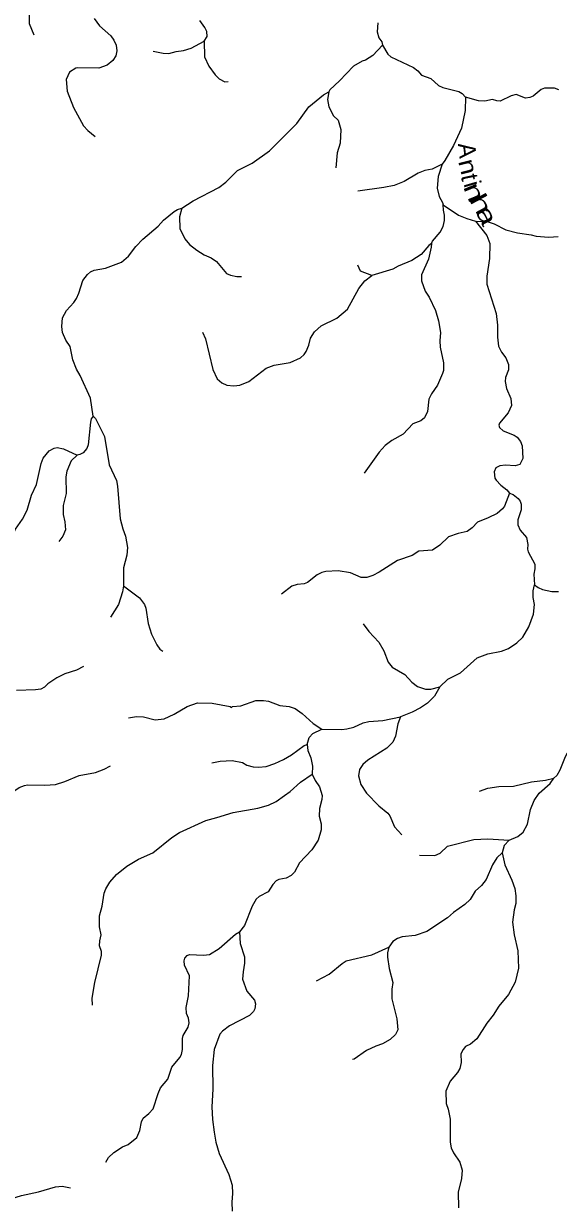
# Model space of a CAD drawing. Extents: x 577 to 602.9, y 7483.8 to 7511.6.
# Drawn here: x 580.64 to 583.13, y 7488.33 to 7493.84 of the extents above; entities that cross this region are included whole.
import ezdxf
from ezdxf.enums import TextEntityAlignment as Align

# ---------------------------------------------------------------- set-up
doc = ezdxf.new("R2010")
doc.units = 0
doc.header["$LTSCALE"] = 0.032
doc.layers.add('61', color=7, linetype='Continuous')
doc.layers.add('7', color=7, linetype='Continuous', lineweight=25)

msp = doc.modelspace()

# ---------------------------------------------------------------- linework, layer by layer
at = {"layer": '7'}
for points in [[(580.6851, 7493.7847), (580.6631, 7493.8367), (580.6631, 7493.8906), (580.668, 7493.911), (580.6892, 7493.9535), (580.6933, 7493.9699), (580.6868, 7494.0516), (580.695, 7494.095), (580.704, 7494.1072), (580.7693, 7494.1399), (580.798, 7494.1644)], [(580.9655, 7493.8612), (580.9892, 7493.8285), (581.0424, 7493.7811), (581.0571, 7493.7615), (581.0677, 7493.7377), (581.071, 7493.7116), (581.0652, 7493.6879), (581.0514, 7493.6666), (581.026, 7493.6446), (580.9868, 7493.6307), (580.8862, 7493.6323), (580.8789, 7493.6299), (580.8495, 7493.6127), (580.8339, 7493.5775), (580.8388, 7493.5236), (580.8683, 7493.4468), (580.9157, 7493.3617), (580.9353, 7493.3397), (580.9688, 7493.3117)], [(581.4764, 7493.7557), (581.4911, 7493.7778), (581.4887, 7493.8007), (581.4797, 7493.8203), (581.4568, 7493.853)], [(582.2856, 7493.8424), (582.2824, 7493.7991), (582.2905, 7493.7721), (582.3036, 7493.7533), (582.3074, 7493.738)], [(581.2392, 7493.7092), (581.2868, 7493.7001), (581.3129, 7493.6993), (581.3473, 7493.7083), (581.3808, 7493.7124), (581.4167, 7493.7239), (581.4764, 7493.7557)], [(581.4764, 7493.7557), (581.4789, 7493.6838), (581.4985, 7493.6405), (581.5279, 7493.5996), (581.5475, 7493.5808), (581.5729, 7493.5677), (581.5888, 7493.5686)], [(582.3074, 7493.738), (582.2619, 7493.6895), (582.2284, 7493.6675), (582.2121, 7493.6625), (582.172, 7493.6397), (582.1066, 7493.571), (582.0625, 7493.5301), (582.0568, 7493.5203)], [(582.3074, 7493.738), (582.3314, 7493.6952), (582.3453, 7493.6838), (582.4508, 7493.6331), (582.4712, 7493.6184), (582.4892, 7493.598), (582.5317, 7493.5824), (582.5676, 7493.5497), (582.5881, 7493.5399), (582.6633, 7493.522), (582.678, 7493.513), (582.6943, 7493.4958)], [(583.1276, 7493.5301), (583.1079, 7493.5367), (583.0614, 7493.5375), (583.0466, 7493.5309), (583.009, 7493.4999), (582.9935, 7493.4942), (582.9731, 7493.4909), (582.9298, 7493.5072), (582.906, 7493.5023), (582.8554, 7493.477), (582.839, 7493.4778), (582.8194, 7493.4844), (582.7834, 7493.477), (582.754, 7493.4786), (582.6943, 7493.4958)], [(581.3734, 7492.9784), (581.4257, 7493.0119), (581.5451, 7493.0748), (581.5786, 7493.1002), (581.6325, 7493.1541), (581.7004, 7493.1876), (581.7813, 7493.2457), (581.9088, 7493.3724), (581.9636, 7493.45), (582.0322, 7493.5064), (582.0568, 7493.5203)], [(582.0568, 7493.5203), (582.051, 7493.4844), (582.0568, 7493.45), (582.0796, 7493.4083), (582.1001, 7493.3879), (582.1132, 7493.3446), (582.1107, 7493.2808), (582.096, 7493.2367), (582.0906, 7493.166)], [(582.6943, 7493.4958), (582.6927, 7493.4337), (582.6747, 7493.3511), (582.6371, 7493.2702), (582.5979, 7493.1999), (582.5848, 7493.1835)], [(582.5848, 7493.1835), (582.5382, 7493.1607), (582.5039, 7493.1541), (582.4728, 7493.1419), (582.4082, 7493.1034), (582.3617, 7493.0846), (582.3134, 7493.074), (582.193, 7493.0579)], [(582.5848, 7493.1835), (582.5668, 7493.1255), (582.5619, 7493.0724), (582.5717, 7493.0323), (582.5873, 7493.0054), (582.5897, 7492.9939)], [(580.96, 7492.0097), (580.9484, 7492.0939), (580.9001, 7492.1986), (580.8821, 7492.228), (580.8658, 7492.2721), (580.8527, 7492.3343), (580.8331, 7492.3637), (580.8176, 7492.3988), (580.8143, 7492.4274), (580.8176, 7492.4683), (580.8364, 7492.5018), (580.8699, 7492.5386), (580.8821, 7492.5574), (580.8936, 7492.5819), (580.9116, 7492.6416), (580.9345, 7492.6702), (580.9475, 7492.6817), (580.9647, 7492.6898), (581.0178, 7492.6988), (581.0914, 7492.7274), (581.1249, 7492.7544), (581.1592, 7492.7994), (581.1919, 7492.8337), (581.2622, 7492.895), (581.2876, 7492.922), (581.3374, 7492.9628), (581.353, 7492.9718), (581.3734, 7492.9784)], [(581.3734, 7492.9784), (581.3628, 7492.9375), (581.3636, 7492.8836), (581.3865, 7492.8361), (581.4094, 7492.81), (581.4421, 7492.783), (581.4772, 7492.7618), (581.5091, 7492.7479), (581.5344, 7492.7299), (581.5802, 7492.6743), (581.5998, 7492.6661), (581.6293, 7492.6604), (581.6505, 7492.6601)], [(582.5358, 7492.8141), (582.5398, 7492.8255), (582.5758, 7492.8672), (582.5897, 7492.8934), (582.5963, 7492.9203), (582.5963, 7492.9457), (582.5913, 7492.9686), (582.5897, 7492.9939)], [(582.5897, 7492.9939), (582.6616, 7492.9465), (582.7001, 7492.9302), (582.7409, 7492.9187)], [(582.7409, 7492.9187), (582.7941, 7492.9163), (582.8268, 7492.9056), (582.8815, 7492.877), (582.9363, 7492.8631), (583, 7492.8549), (583.0229, 7492.8484), (583.0818, 7492.8435), (583.1251, 7492.8469)], [(582.7409, 7492.9187), (582.7924, 7492.8517), (582.8071, 7492.8133), (582.8055, 7492.7438), (582.7924, 7492.662), (582.7924, 7492.6253), (582.8366, 7492.4879), (582.8431, 7492.434), (582.8431, 7492.3776), (582.848, 7492.3359), (582.8611, 7492.3073), (582.8815, 7492.2819), (582.8938, 7492.2509), (582.8938, 7492.2255), (582.8799, 7492.1904), (582.8791, 7492.1716), (582.8848, 7492.1381), (582.9052, 7492.0923), (582.9085, 7492.0588), (582.8922, 7492.0253), (582.8513, 7491.9771), (582.8488, 7491.9672), (582.8521, 7491.9566), (582.8693, 7491.9411), (582.9208, 7491.9215), (582.9347, 7491.9117), (582.9494, 7491.8912), (582.9575, 7491.8716), (582.9608, 7491.8128), (582.9469, 7491.785), (582.9248, 7491.7784), (582.8799, 7491.7809), (582.8529, 7491.7776), (582.8349, 7491.7694), (582.8268, 7491.7506), (582.8308, 7491.7212), (582.8366, 7491.7122), (582.8578, 7491.6877), (582.8856, 7491.6673), (582.8987, 7491.6517)], [(582.5358, 7492.8141), (582.5341, 7492.7961), (582.5219, 7492.7413), (582.4884, 7492.6678), (582.4884, 7492.6408), (582.5063, 7492.5917), (582.5243, 7492.564), (582.5537, 7492.5018), (582.5685, 7492.4544), (582.5766, 7492.3997), (582.5734, 7492.3612), (582.5758, 7492.331), (582.5913, 7492.2574), (582.5913, 7492.2231), (582.5873, 7492.2084), (582.5627, 7492.1544), (582.5358, 7492.1144), (582.5227, 7492.0882), (582.5161, 7492.031), (582.5022, 7492.0016), (582.4859, 7491.9885), (582.4491, 7491.9738), (582.4033, 7491.9264), (582.351, 7491.8969), (582.32, 7491.8724), (582.2914, 7491.8414), (582.2215, 7491.7441)], [(582.5358, 7492.8141), (582.5227, 7492.8043), (582.4875, 7492.7626), (582.4442, 7492.734), (582.3796, 7492.7078), (582.3559, 7492.6947), (582.2577, 7492.6652)], [(582.2577, 7492.6652), (582.2055, 7492.6849), (582.1918, 7492.7134)], [(581.469, 7492.4016), (581.4829, 7492.3702), (581.5181, 7492.2272), (581.5369, 7492.1839), (581.559, 7492.1642), (581.5818, 7492.1544), (581.6154, 7492.1512), (581.6432, 7492.1544), (581.6848, 7492.1716), (581.7649, 7492.2337), (581.8025, 7492.2476), (581.8778, 7492.2599), (581.926, 7492.2811), (581.9423, 7492.2967), (581.9513, 7492.3114), (581.9636, 7492.3408), (581.9718, 7492.3735), (581.9906, 7492.4021), (582.0224, 7492.4299), (582.0952, 7492.4659), (582.1442, 7492.5076), (582.1965, 7492.604), (582.2246, 7492.6395), (582.2577, 7492.6652)], [(580.96, 7492.0097), (580.9516, 7491.9967), (580.9484, 7491.982), (580.9369, 7491.8757), (580.9312, 7491.8593), (580.914, 7491.8397), (580.8985, 7491.8307), (580.8862, 7491.8283)], [(580.96, 7492.0097), (580.9712, 7491.9991), (581.0129, 7491.9149), (581.035, 7491.7833), (581.0685, 7491.7106), (581.0742, 7491.6844), (581.0865, 7491.5316), (581.0979, 7491.4842), (581.1102, 7491.4506), (581.12, 7491.3975), (581.1167, 7491.3624), (581.102, 7491.3027), (581.102, 7491.2201)], [(580.56, 7491.1903), (580.5658, 7491.2226), (580.5658, 7491.2855), (580.5854, 7491.3501), (580.5871, 7491.3656), (580.5871, 7491.3861), (580.5805, 7491.4098), (580.5822, 7491.4449), (580.5985, 7491.4833), (580.6312, 7491.5307), (580.6525, 7491.5724), (580.6729, 7491.6419), (580.6966, 7491.6918), (580.7178, 7491.7899), (580.7277, 7491.8144), (580.7555, 7491.8479), (580.7792, 7491.861), (580.7922, 7491.8643), (580.8217, 7491.8577), (580.8862, 7491.8283)], [(580.8862, 7491.8283), (580.8576, 7491.8013), (580.8372, 7491.7539), (580.8331, 7491.7277), (580.8347, 7491.6493), (580.8208, 7491.5937), (580.82, 7491.5512), (580.829, 7491.5169), (580.8307, 7491.4809), (580.8192, 7491.4515), (580.8004, 7491.4261)], [(582.8987, 7491.6517), (582.875, 7491.5904), (582.866, 7491.5782), (582.8407, 7491.5569), (582.7998, 7491.5357), (582.7491, 7491.516), (582.7246, 7491.4891), (582.7009, 7491.4719), (582.6592, 7491.4637), (582.6151, 7491.4474), (582.5734, 7491.4081), (582.5398, 7491.3861), (582.4761, 7491.3803), (582.4458, 7491.3607), (582.3764, 7491.3378), (582.2914, 7491.2831), (582.2627, 7491.2675), (582.2341, 7491.2586), (582.208, 7491.2586), (582.1589, 7491.2806), (582.1009, 7491.2888), (582.0437, 7491.2863), (582.0241, 7491.2814), (582.0036, 7491.2708), (581.9587, 7491.2357), (581.9431, 7491.2291), (581.9096, 7491.2259), (581.8851, 7491.2177), (581.8371, 7491.1807)], [(582.8987, 7491.6517), (582.9159, 7491.6444), (582.9396, 7491.6256), (582.9486, 7491.6133), (582.9526, 7491.6002), (582.9526, 7491.5741), (582.9379, 7491.5267), (582.9379, 7491.5038), (582.9477, 7491.4793), (582.9772, 7491.4449), (582.9837, 7491.4114), (582.9821, 7491.391), (582.9853, 7491.3779), (583.0164, 7491.3199), (583.0172, 7491.2994), (583.0115, 7491.2733), (583.0148, 7491.2242)], [(581.102, 7491.2201), (581.0971, 7491.1915), (581.0775, 7491.1319), (581.0416, 7491.074)], [(581.102, 7491.2201), (581.1756, 7491.1637), (581.1993, 7491.1327), (581.2058, 7491.1147), (581.2165, 7491.0436), (581.232, 7490.9937), (581.2565, 7490.9447), (581.2712, 7490.9251), (581.2846, 7490.9158)], [(582.5734, 7490.7493), (582.611, 7490.7853), (582.6698, 7490.8147), (582.7475, 7490.8834), (582.7973, 7490.903), (582.8619, 7490.9144), (582.8946, 7490.9275), (582.933, 7490.9537), (582.9608, 7490.9806), (582.9886, 7491.0289), (583.0099, 7491.0869), (583.0148, 7491.1327), (583.0082, 7491.1654), (583.009, 7491.1964), (583.0148, 7491.2242)], [(583.0148, 7491.2242), (583.0327, 7491.211), (583.0515, 7491.203), (583.0957, 7491.1932), (583.1268, 7491.1929)], [(582.2174, 7491.0424), (582.2431, 7491.006), (582.2897, 7490.9577), (582.3134, 7490.9161), (582.333, 7490.8646), (582.3527, 7490.8409), (582.4107, 7490.8065), (582.4442, 7490.7706), (582.4704, 7490.7501), (582.5072, 7490.7379), (582.5325, 7490.7387), (582.5734, 7490.7493)], [(580.9151, 7490.8432), (580.8821, 7490.8261), (580.829, 7490.8098), (580.7906, 7490.791), (580.7489, 7490.7624), (580.7342, 7490.7477), (580.717, 7490.7387), (580.6917, 7490.7346), (580.6026, 7490.7313)], [(582.5734, 7490.7493), (582.5488, 7490.7052), (582.5161, 7490.6725), (582.4843, 7490.6512), (582.4458, 7490.6316), (582.3903, 7490.6087)], [(581.1242, 7490.6041), (581.1625, 7490.6112), (581.1944, 7490.6095), (581.2492, 7490.5956), (581.2909, 7490.6005), (581.3374, 7490.6218), (581.3979, 7490.6578), (581.4453, 7490.6741), (581.514, 7490.6725), (581.5982, 7490.6578), (581.6047, 7490.652), (581.6096, 7490.6578), (581.6481, 7490.6602), (581.7175, 7490.6847), (581.7535, 7490.6856), (581.7764, 7490.6815), (581.8287, 7490.6618), (581.8728, 7490.6569), (581.9006, 7490.6479), (581.9333, 7490.6251), (581.984, 7490.5777), (582.0248, 7490.5526)], [(582.0248, 7490.5526), (582.1181, 7490.5499), (582.141, 7490.5531), (582.1745, 7490.5613), (582.217, 7490.5809), (582.2439, 7490.5883), (582.3085, 7490.5924), (582.3903, 7490.6087)], [(582.3903, 7490.6087), (582.378, 7490.5768), (582.3674, 7490.5196), (582.3551, 7490.4918), (582.3273, 7490.4632), (582.2382, 7490.4076), (582.2153, 7490.388), (582.2006, 7490.3643), (582.1957, 7490.3349), (582.2063, 7490.2948), (582.2333, 7490.254), (582.2897, 7490.1943), (582.3322, 7490.1608), (582.3412, 7490.1485), (582.3625, 7490.0962), (582.3976, 7490.0602)], [(581.957, 7490.4812), (581.966, 7490.5131), (581.9824, 7490.5319), (582.0248, 7490.5526)], [(583.2289, 7490.527), (583.2028, 7490.4975), (583.1766, 7490.4567), (583.1578, 7490.4223), (583.1333, 7490.3602), (583.1186, 7490.3365), (583.1047, 7490.3243)], [(581.5134, 7490.3955), (581.5508, 7490.4027), (581.6072, 7490.406), (581.6554, 7490.3962), (581.6759, 7490.3847), (581.7053, 7490.3766), (581.7306, 7490.3749), (581.7649, 7490.3782), (581.8066, 7490.3913), (581.8467, 7490.4101), (581.8835, 7490.4322), (581.9431, 7490.4763), (581.957, 7490.4812)], [(581.957, 7490.4812), (581.9603, 7490.4526), (581.9734, 7490.4183), (581.9816, 7490.3798), (581.9799, 7490.3422)], [(580.5462, 7490.2294), (580.5625, 7490.2442), (580.6157, 7490.2809), (580.6402, 7490.2899), (580.6541, 7490.2932), (580.7358, 7490.2907), (580.7841, 7490.2948), (580.8282, 7490.3079), (580.8944, 7490.3357), (580.9704, 7490.3504), (581.0121, 7490.3659), (581.0406, 7490.3818)], [(580.957, 7489.267), (580.9549, 7489.2992), (580.9672, 7489.372), (580.999, 7489.4995), (580.999, 7489.5158), (580.9892, 7489.542), (580.9909, 7489.5665), (580.9982, 7489.5943), (580.9892, 7489.6319), (580.9892, 7489.6826), (581.0023, 7489.7275), (581.0121, 7489.788), (581.0195, 7489.8085), (581.0375, 7489.8395), (581.0693, 7489.8747), (581.1167, 7489.9139), (581.1715, 7489.9458), (581.2385, 7489.976), (581.3268, 7490.0472), (581.362, 7490.0709), (581.4854, 7490.1264), (581.5361, 7490.1403), (581.6121, 7490.164), (581.7265, 7490.1837), (581.7772, 7490.1984), (581.8115, 7490.2155), (581.8508, 7490.2425), (581.8778, 7490.2621), (581.9252, 7490.3055), (581.9799, 7490.3422)], [(581.9799, 7490.3422), (581.9938, 7490.312), (582.0134, 7490.2826), (582.0257, 7490.2433), (582.0249, 7490.2237), (582.0143, 7490.182), (582.0126, 7490.1469), (582.0224, 7490.1109), (582.0224, 7490.0831), (582.0077, 7490.0349), (581.9775, 7489.9891), (581.9203, 7489.9286), (581.8982, 7489.8861), (581.8818, 7489.8698), (581.8589, 7489.8575), (581.8246, 7489.8518), (581.8115, 7489.8453), (581.7968, 7489.8289), (581.7756, 7489.7946), (581.7323, 7489.7725), (581.7192, 7489.7602), (581.7004, 7489.7275), (581.6652, 7489.6376), (581.6415, 7489.6082)], [(582.759, 7490.2627), (582.7973, 7490.2777), (582.8488, 7490.285), (582.9167, 7490.2867), (583.0017, 7490.3063), (583.0654, 7490.3144), (583.1047, 7490.3243)], [(582.8971, 7490.0349), (582.9371, 7490.0512), (582.9624, 7490.0725), (582.9821, 7490.1101), (582.996, 7490.1779), (583.0131, 7490.2196), (583.0368, 7490.2531), (583.0883, 7490.2989), (583.1047, 7490.3243)], [(582.479, 7489.9647), (582.5505, 7489.9638), (582.575, 7489.9744), (582.6093, 7490.0063), (582.7328, 7490.0382), (582.7982, 7490.0414), (582.8971, 7490.0349)], [(582.8971, 7490.0349), (582.8742, 7490.0104), (582.8644, 7489.976)], [(582.8644, 7489.976), (582.8398, 7489.9523), (582.8186, 7489.9205), (582.79, 7489.851), (582.7679, 7489.824), (582.7393, 7489.797), (582.7156, 7489.7586), (582.6903, 7489.7349), (582.6371, 7489.6981), (582.6093, 7489.6736), (582.5129, 7489.609), (582.4597, 7489.591), (582.3993, 7489.5853), (582.3764, 7489.5771), (582.3551, 7489.5633), (582.3363, 7489.5363)], [(582.8644, 7489.976), (582.8774, 7489.9205), (582.9101, 7489.8485), (582.9232, 7489.8101), (582.9281, 7489.775), (582.9281, 7489.7406), (582.9199, 7489.7096), (582.9126, 7489.6523), (582.9199, 7489.5943), (582.9379, 7489.5191), (582.9404, 7489.439), (582.9248, 7489.3728), (582.8946, 7489.3164), (582.8496, 7489.2616), (582.8219, 7489.2191), (582.7924, 7489.1832), (582.7458, 7489.1096), (582.7172, 7489.0851), (582.6943, 7489.0736), (582.6821, 7489.0597), (582.6715, 7489.0401), (582.6731, 7488.9992), (582.6665, 7488.9714), (582.6567, 7488.9526), (582.6224, 7488.9118), (582.6028, 7488.8652), (582.6044, 7488.808), (582.6134, 7488.7818), (582.6224, 7488.736), (582.6224, 7488.6281), (582.6273, 7488.602), (582.6371, 7488.5783), (582.6674, 7488.535), (582.6788, 7488.4974), (582.6747, 7488.4589), (582.66, 7488.3952), (582.6616, 7488.3216)], [(581.0195, 7488.5352), (581.0309, 7488.557), (581.0563, 7488.5807), (581.0963, 7488.6061), (581.1233, 7488.6175), (581.1642, 7488.6502), (581.178, 7488.6821), (581.1854, 7488.723), (581.1928, 7488.7401), (581.2197, 7488.7614), (581.2402, 7488.7834), (581.2622, 7488.8554), (581.2737, 7488.8807), (581.3072, 7488.9224), (581.326, 7488.978), (581.3644, 7489.0221), (581.3718, 7489.0368), (581.3767, 7489.0597), (581.3767, 7489.1104), (581.3799, 7489.1251), (581.4028, 7489.1644), (581.4077, 7489.1848), (581.4045, 7489.2052), (581.3955, 7489.2281), (581.393, 7489.2551), (581.4045, 7489.3099), (581.4094, 7489.403), (581.3849, 7489.4521), (581.3832, 7489.4733), (581.3873, 7489.4848), (581.3979, 7489.497), (581.4086, 7489.5019), (581.474, 7489.4987), (581.5017, 7489.5028), (581.5467, 7489.5297), (581.6235, 7489.5976), (581.6415, 7489.6082)], [(581.6415, 7489.6082), (581.6448, 7489.5534), (581.6644, 7489.4913), (581.6652, 7489.4619), (581.6579, 7489.421), (581.6562, 7489.3867), (581.6759, 7489.3311), (581.7118, 7489.2894), (581.7159, 7489.2731), (581.7135, 7489.2494), (581.7069, 7489.2363), (581.6873, 7489.2175), (581.5949, 7489.1701), (581.563, 7489.1456), (581.55, 7489.1308), (581.5238, 7489.0597), (581.5156, 7488.9853), (581.5173, 7488.8758), (581.5124, 7488.7933), (581.5156, 7488.7344), (581.5238, 7488.6747), (581.532, 7488.6281), (581.5467, 7488.5758), (581.5917, 7488.4769), (581.6072, 7488.4279), (581.6096, 7488.3886), (581.6056, 7488.3494), (581.6072, 7488.3061)], [(582, 7489.3791), (582.0592, 7489.4104), (582.1189, 7489.4611), (582.1377, 7489.4725), (582.257, 7489.5011), (582.3363, 7489.5363)], [(582.3363, 7489.5363), (582.3298, 7489.5093), (582.3298, 7489.4905), (582.338, 7489.4374), (582.3559, 7489.372), (582.351, 7489.3401), (582.351, 7489.296), (582.3739, 7489.202), (582.3788, 7489.1513), (582.3682, 7489.1292), (582.3437, 7489.1063), (582.3077, 7489.0859), (582.2766, 7489.0761), (582.2333, 7489.0548), (582.1753, 7489.0148), (582.1671, 7489.0139)], [(580.3696, 7488.369), (580.4252, 7488.3494), (580.4775, 7488.3412), (580.5266, 7488.3486), (580.6263, 7488.3805), (580.7064, 7488.3968), (580.7849, 7488.4197), (580.8159, 7488.423), (580.8548, 7488.4155)]]:
    msp.add_lwpolyline(points, dxfattribs=at)

# ---------------------------------------------------------------- texts
at = {"layer": '61'}
for s, rotation, p in [('A', 276.81, (582.6622, 7493.243)), ('t', 281.651, (582.6748, 7493.1146)), ('i', 286.491, (582.6873, 7493.0801))]:
    msp.add_text(s, height=0.08, rotation=rotation, dxfattribs=at).set_placement(p, align=Align.CENTER)
for s, rotation, width, p in [('n', 284.038, 1.2, (582.6676, 7493.1623)), ('n', 292.401, 1.45, (582.698, 7493.038)), ('h', 298.461, 1.6, (582.7311, 7492.9782)), ('a', 296.172, 1.45, (582.7565, 7492.9274))]:
    msp.add_text(s, height=0.08, rotation=rotation, dxfattribs=dict(at, width=width)).set_placement(p, align=Align.CENTER)

doc.saveas('drawing.dxf')
